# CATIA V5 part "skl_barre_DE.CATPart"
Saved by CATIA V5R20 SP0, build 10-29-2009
Part number: skl_barre_DE
Publications: "Axe_pivot_DE_E", "Axe_pivot_DE_D", "Droite_DE"
Bounding box of the stored display mesh (mm): x 0 to 5, y 94.005 to 130.995, z 44.008 to 205.992
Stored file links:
  D:\Dropbox\IAO_2012\IAO_2012_742_prousseau\skl_barre_DE.CATPart
  D:\Dropbox\IAO_2012\IAO_2012_742_prousseau\skl_IAO.CATProduct
  D:\Dropbox\IAO_2012\IAO_2012_742_prousseau\skl_barre_CD.CATPart
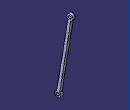
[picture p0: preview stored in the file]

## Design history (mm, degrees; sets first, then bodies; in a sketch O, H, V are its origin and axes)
Set1
  Point1 "Point_D": linked copy from another document
Set2
  Line1 "Droite_DE": type PtPt, FirstPoint Point2, SecondPoint Point3
  Point2 "Point_D": stored without definition
  Point3 "Point_E": stored without definition
  Line2 "Axe_pivot_DE_D": type Normal, RefPoint Point2, RefSkin Plane1, Start -20, End 20
  Plane1 "Plan_Ref": stored without definition
  Line3 "Axe_pivot_DE_E": type Normal, RefPoint Point3, RefSkin Plane1, Start -20, End 20
Body1 (main body)
  Sketch1 on Plane1, origin (0, 0, 0), H (0, -0.1644, -0.9864), V (0, 0.9864, -0.1644)
    line L1 (-212.6325, 87.4194) -> (-70.9557, 87.4194)
    reference projected line E1 (-217.8287, 90.4194) -> (-65.7596, 90.4194) from Line1
    arc A1 centre (-217.8287, 90.4194) radius 6 from (-212.6325, 93.4194) to (-212.6325, 87.4194) ccw
    point P1 (-217.8287, 90.4194)
    circle A2 centre (-217.8287, 90.4194) radius 3
    point P2 (-217.8287, 90.4194)
    reference projected point E2 (-217.8287, 90.4194) from Point1
    reference projected point E3 (-217.8287, 90.4194) from Point1
    circle A3 centre (-65.7596, 90.4194) radius 3
    point P5 (-65.7596, 90.4194)
    reference projected point E4 (-65.7596, 90.4194) from Point3
    arc A4 centre (-65.7596, 90.4194) radius 6 from (-70.9557, 87.4194) to (-70.9557, 93.4194) ccw
    point P6 (-65.7596, 90.4194)
    reference projected point E5 (-65.7596, 90.4194) from Point3
    line L2 (-70.9557, 93.4194) -> (-212.6325, 93.4194)
    distance L1 E1 = 3
    radius A1 = 6
    radius A2 = 3
    radius A4 = 6
    radius A3 = 3
    horizontal: L1 H, L2 H
    coincidence: P2 E2, P1 E3, P5 E4, P6 E5
  Pad1: profile Sketch1, direction (1, 0, 0), length 5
